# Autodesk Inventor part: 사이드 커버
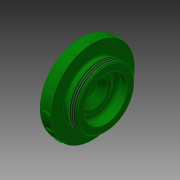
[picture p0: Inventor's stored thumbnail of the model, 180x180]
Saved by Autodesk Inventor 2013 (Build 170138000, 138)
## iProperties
Created: 2016-08
Part Number: 사이드 커버
Material: 스테인리스강
Document SubType Name: Modeling
Designer: mduedu
Density: 8.08 g/cm^3
Author: mduedu
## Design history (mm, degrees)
sketch "스케치1"
  geometry: L1 (3, 0)-(10, 0); L2 (4, 24)-(4, 32); L3 (4, 32)-(14, 32); L4 (14, 32)-(14, 22.5); L5 (14, 22.5)-(24, 22.5); L6 (24, 22.5)-(24, 16.5); L7 (16, 11)-(10, 5); L8 (10, 5)-(10, 0); L9 (4, 24)-(0, 21.199); L10 (0, 21.199)-(0, 17.059); L11 (24, 16.5)-(16, 16.5); L12 (16, 16.5)-(16, 11); A1 r 50 centre (-47, 0) between (3, 0) and (0, 17.059); 1 further point
  constraints: 25 end point, 4 parallel, 4 perpendicular, 2 point on circle, 2 point on line, 1 centre point, 1 horizontal, 1 horizontal alignment, 1 vertical
  dimensions: "d2" = 64 diameter of L3 L1; "d3" = 45 diameter of L5 L1; "d5" = 6 distance of L5.end L6.end; "d35" = 48 diameter of L2.start L1; "d36" = 10 distance of L2.end L3.end; "d37" = 24 distance between parallel lines of L6 L10; "d39" = 125 deg angle of L10 L9; "d42" = 10 distance between parallel lines of L6 L4; "d44" = 3 distance of L1.start point (0, 0); "d45" = 50 radius of A1; "d47" = 135 deg angle of L7 L12; "d49" = 22 diameter of L7.start L1; "d50" = 8 distance between parallel lines of L6 L12; "d51" = 6 distance between parallel lines of L12 L8
revolve "회전1" sketch "스케치1" stored, may be unused: angle "d6" = 90 deg
fillet "모깎기1" dims "d7" = 3
sketch "스케치2"
  geometry: L1 (14, -32)-(14, 32) reference; L2 (14, 22.5)-(24, 22.5) reference; L3 (0, 0)-(14, 0); L4 (14, 22.5)-(18.492, 22.5); L5 (18.492, 22.5)-(16.5, 21.35); L6 (16.5, 21.35)-(14, 21.35); L7 (14, 21.35)-(14, 22.5)
  constraints: 10 end point, 1 horizontal, 1 midpoint, 1 parallel, 1 vertical
  dimensions: "d9" = 42.7 diameter of L6 L3; "d31" = 30 deg angle of L2 L5; "d32" = 2.5 distance from line of L1 L5.end
revolve "회전2" sketch "스케치2" stored, may be unused: angle "d10" = 90 deg
fillet "모깎기2" dims "d11" = 3, "d33" = 0.8
feature "스레드1" dims "d12" = 10, "d13" = 0
chamfer "모따기1" distance "d14" = 1; stored, may be unused: second distance "d15" = 2, angle "d16" = 45 deg
node "작업 평면1"
sketch "스케치3"
  geometry: L1 (-8, -1)-(-13, -1); L2 (-13, -1)-(-13, 1); L3 (-13, 1)-(-8, 1); L4 (-8, 1)-(-8, -1); 2 further points
  constraints: 8 end point, 2 parallel, 1 horizontal, 1 horizontal alignment, 1 midpoint, 1 perpendicular
  dimensions: "d18" = 2 distance of L3.end L1.start; "d20" = 5 distance of L1.start L1.end; "d41" = 8 distance from line of point (0, 0) L4
extrude "돌출1" join sketch "스케치3" stored distance "d22" = 10; taper "d23" = 0 deg
fillet "모깎기3" dims "d24" = 1
fillet "모깎기4" dims "d25" = 0.2
node "솔리드1"
pattern_circular "원형 패턴1" dims "d27" = 360 deg
other parameters: "d17" = 32.5
